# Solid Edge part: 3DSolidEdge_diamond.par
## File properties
Author: Administrator
Template: Normal.par
Last saved by: Administrator
Revision: 5
Application: Solid Edge
Accuracy: 0.990
Agile_Description: Diamond Control Pad
Modeled_By: L. Conard
Part_Number: ITEM-SE-00010
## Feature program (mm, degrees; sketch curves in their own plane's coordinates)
body "unnamed Body 1"
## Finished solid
Body 1: solid body, 10 faces, 20 edges, 12 vertices.
  Faces by surface: plane 6, cylinder 4
  Edges by curve: line 16, ellipse 4
Bounding box of the edges (mm): 28.000 x 28.000 x 3.000, from (-19.7427, 35.9821, 0) to (8.2573, 63.9821, 3).
Cylindrical faces by radius (mm): R0.25 x4
Planar faces by outward normal: +z 1, -z 1, oblique 4
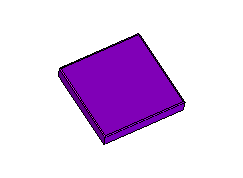
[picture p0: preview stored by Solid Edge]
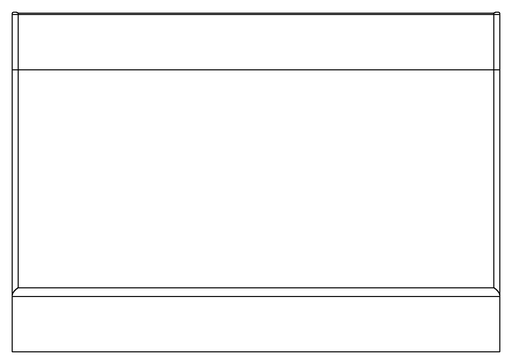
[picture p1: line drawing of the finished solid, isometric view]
